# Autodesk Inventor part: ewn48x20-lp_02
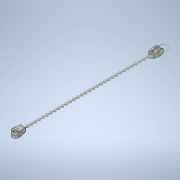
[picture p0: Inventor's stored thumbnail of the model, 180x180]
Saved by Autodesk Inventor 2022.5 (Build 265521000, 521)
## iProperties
Created: 2021-08
Part Number: ewn48x20-lp_02
Material: 一般
Document SubType Name: Modeling
Designer: ImaoCorp
Density: 1 g/cm^3
Appearance: 既定
Author: ImaoCorp
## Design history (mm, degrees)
feature "ewn48x20-lp_02"
node "ソリッド1"
